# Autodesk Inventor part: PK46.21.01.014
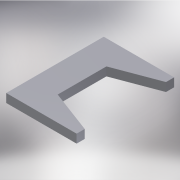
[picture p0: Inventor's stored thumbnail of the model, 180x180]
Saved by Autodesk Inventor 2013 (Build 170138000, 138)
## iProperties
Created: 2005-03
Part Number: PK46.21.01.014
Material: Steel, Mild
Document SubType Name: Modeling
Designer: salex
Manufacturer: Standard
Standards Organization: Custom
Density: 7.86 g/cm^3
Author: salex
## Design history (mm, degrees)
sketch "Эскиз1"
  geometry: L1 (0, 0)-(130, 0); L2 (130, 0)-(130, 15); L3 (130, 15)-(50, 45); L4 (50, 45)-(50, 135); L5 (50, 135)-(130, 165); L6 (130, 165)-(130, 180); L7 (130, 180)-(0, 180); L8 (0, 180)-(0, 0)
  constraints: 16 end point, 3 parallel, 2 collinear, 2 equal length, 1 horizontal, 1 perpendicular, 1 other
  dimensions: "d0" = 180 distance of L7.end L1.start; "d1" = 15 distance of L5.end L6.end; "d2" = 130 distance of L6.end L7.end; "d3" = 50 distance between parallel lines of L8 L4; "d4" = 45 distance from line of L1 L3.end
extrude "Выдавливание1" new body sketch "Эскиз1" distance "d5" = 16; taper "d6" = 0 deg
body "Solid1"
